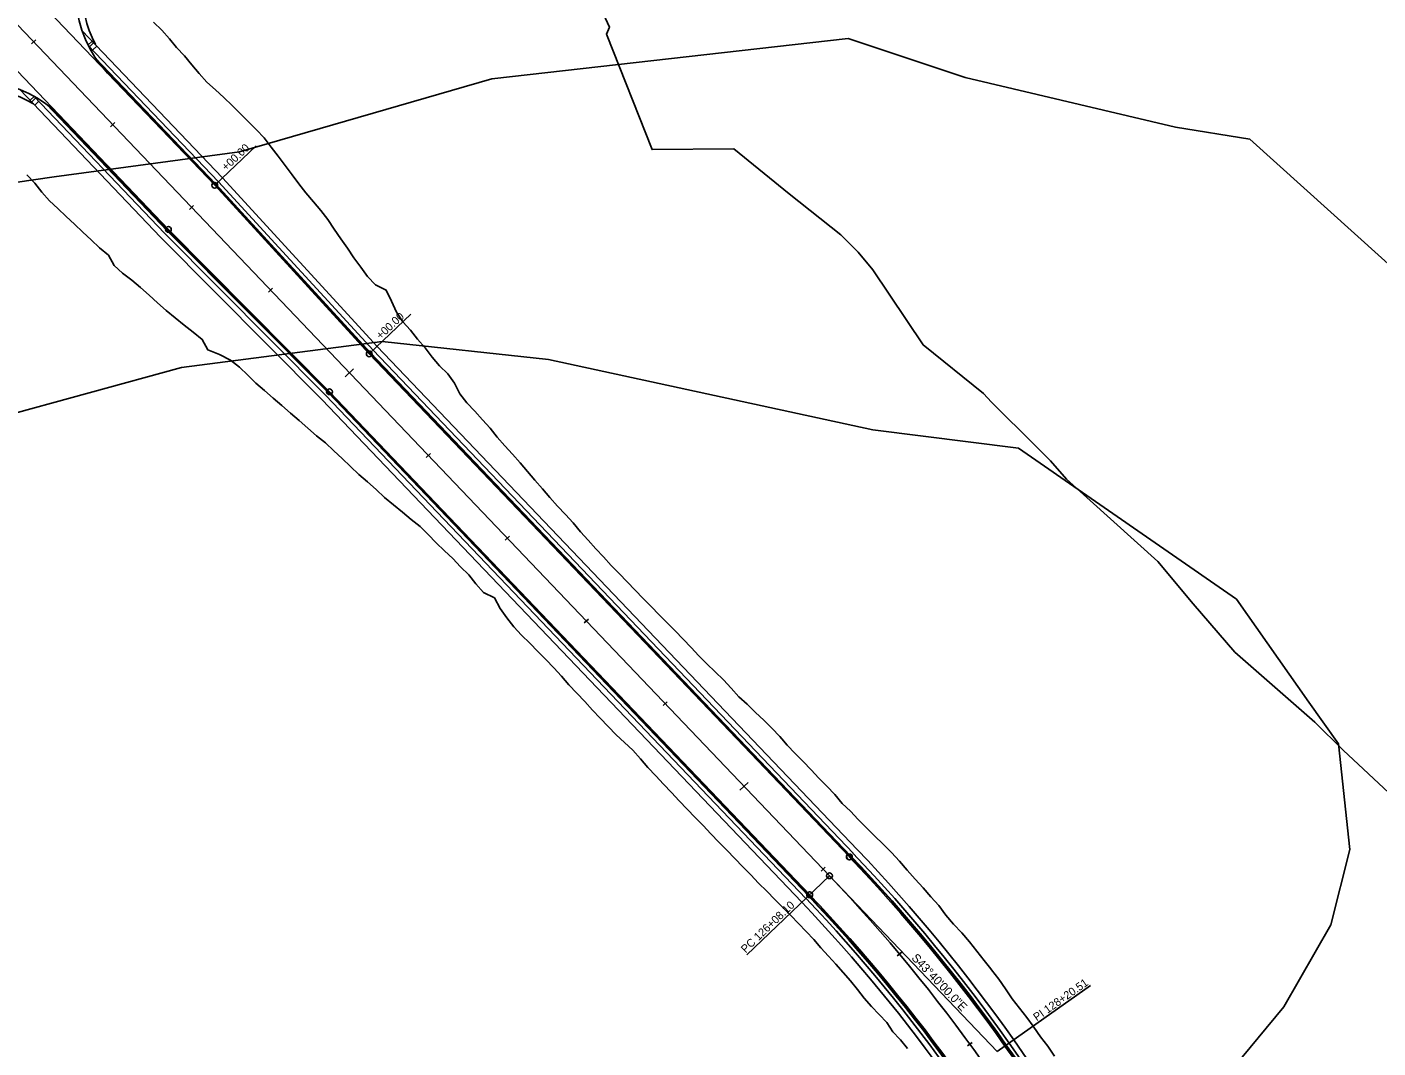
# Model space of a CAD drawing. Extents: x 1300404 to 1323571, y 234004 to 252077.
# Drawn here: x 1311251 to 1312432, y 239629 to 240521 of the extents above; entities that cross this region are included whole.
import ezdxf

# ---------------------------------------------------------------- set-up
doc = ezdxf.new("R2010")
doc.units = 0
for name, color, linetype in [('R_Const Limits', 7, 'Continuous'), ('R_Curb', 7, 'Continuous'), ('R_Flooplain', 7, 'Continuous'), ('R_Horz Alg Annot', 7, 'Continuous'), ('R_Horz Alg Annot Leader', 7, 'Continuous'), ('R_Horz Alg Major Ticks', 7, 'Continuous'), ('R_Horz Alg Minor Ticks', 7, 'Continuous'), ('R_Horz Alg Tangents', 7, 'Continuous'), ('R_Horz Alg Tangents Text', 7, 'Continuous'), ('R_Lane Edge', 7, 'Continuous'), ('R_Proposed', 7, 'Continuous'), ('R_Shoulder', 7, 'Continuous'), ('R_Sidewalk Edge', 7, 'Continuous')]:
    doc.layers.add(name, color=color, linetype=linetype)

msp = doc.modelspace()

# ---------------------------------------------------------------- linework, layer by layer
at = {"layer": 'R_Const Limits'}
for points in [[(1312468.4, 239826.8), (1312401.8, 239888.9), (1312377.1, 239913.6), (1312307.2, 239974.6), (1312270.6, 240016.9), (1312239.7, 240054), (1312160, 240125.9), (1312146, 240142), (1312132.7, 240155.1), (1312094.4, 240193.4), (1312087.2, 240200.9), (1312034.5, 240243.4), (1311990.5, 240309.1), (1311977.8, 240324.5), (1311962.6, 240339.6), (1311917.3, 240375.7), (1311869, 240414.8), (1311797.5, 240414.3), (1311757.6, 240515.1), (1311760.1, 240521.2), (1311745.1, 240554.6)], [(1311361.5, 240525.7), (1311368.6, 240518.6), (1311375.3, 240511.2), (1311381.6, 240503.4), (1311388.6, 240496.2), (1311395, 240488.5), (1311401.3, 240480.7), (1311408.1, 240473.3), (1311415.5, 240466.6), (1311422.8, 240459.8), (1311430.1, 240452.9), (1311437.2, 240445.8), (1311444.2, 240438.7), (1311451.3, 240431.6), (1311458.2, 240424.5), (1311458.2, 240424.4), (1311464.4, 240416.5), (1311470.4, 240408.4), (1311476.4, 240400.3), (1311482.5, 240392.3), (1311488.6, 240384.3), (1311494.7, 240376.3), (1311501.2, 240368.6), (1311507.7, 240361), (1311513.9, 240353.1), (1311519.5, 240344.7), (1311525.2, 240336.3), (1311531, 240328), (1311536.5, 240319.5), (1311542.6, 240311.4), (1311548.4, 240303.2), (1311555.4, 240296), (1311565, 240291.3), (1311569.4, 240281.7), (1311573.8, 240272.1), (1311579.3, 240263.5), (1311586.2, 240256.2), (1311592.4, 240248.4), (1311599.1, 240240.9), (1311605, 240232.7), (1311611.5, 240225.1), (1311618.8, 240218.2), (1311624.6, 240209.9), (1311629.3, 240200.7), (1311635.5, 240192.8), (1311642.3, 240185.4), (1311649, 240177.9), (1311655.8, 240170.6), (1311662, 240162.8), (1311668.6, 240155.2), (1311675.4, 240147.9), (1311682, 240140.4), (1311688.4, 240132.6), (1311694.9, 240125), (1311701.5, 240117.5), (1311708.1, 240109.9), (1311714.8, 240102.5), (1311721.6, 240095.2), (1311728.3, 240087.7), (1311734.8, 240080.1), (1311741.5, 240072.7), (1311748.1, 240065.2), (1311755, 240058), (1311761.7, 240050.6), (1311768.7, 240043.4), (1311775.7, 240036.2), (1311782.5, 240029), (1311789.5, 240021.8), (1311796.5, 240014.6), (1311803.5, 240007.5), (1311810.7, 240000.5), (1311817.7, 239993.4), (1311824.7, 239986.2), (1311831.5, 239978.9), (1311838.2, 239971.5), (1311845.3, 239964.5), (1311852.6, 239957.6), (1311859.8, 239950.6), (1311866.5, 239943.2), (1311873.3, 239935.8), (1311880.7, 239929.1), (1311887.9, 239922.1), (1311895.2, 239915.3), (1311902.3, 239908.2), (1311909.1, 239900.9), (1311911, 239899), (1311915.7, 239893.4), (1311922.6, 239886.2), (1311929.5, 239879), (1311936.5, 239871.8), (1311943.4, 239864.6), (1311950.4, 239857.4), (1311957.2, 239850.1), (1311963.8, 239842.5), (1311971.1, 239835.6), (1311977.8, 239828.3), (1311984.9, 239821.2), (1311992.1, 239814.2), (1311999.5, 239806.9), (1312006.7, 239799.4), (1312013.7, 239791.8), (1312020.6, 239784), (1312027.6, 239776.3), (1312034.5, 239768.6), (1312041.3, 239760.8), (1312048.3, 239753.1), (1312054.3, 239744.6), (1312061, 239736.7), (1312068.3, 239729.3), (1312075, 239721.3), (1312081.4, 239713.2), (1312088, 239705.1), (1312093.8, 239697.8), (1312094.4, 239697), (1312100.6, 239688.7), (1312106.6, 239680.2), (1312112.3, 239671.5), (1312118.7, 239663.4), (1312125.2, 239655.2), (1312130.8, 239647.7), (1312131.3, 239646.9), (1312137.1, 239638.2), (1312143.6, 239630.1), (1312149.3, 239621.5)], [(1312020.9, 239628.2), (1312014.7, 239635.6), (1312014.1, 239636.3), (1312008, 239642.7), (1312002.7, 239650.8), (1311996.1, 239657.9), (1311989.4, 239664.9), (1311982.9, 239672.1), (1311977, 239679.7), (1311970.9, 239687.3), (1311964.5, 239694.5), (1311958.2, 239701.9), (1311951.6, 239708.9), (1311945.1, 239716.1), (1311938.8, 239723.4), (1311932.2, 239730.4), (1311925.5, 239737.4), (1311918.7, 239744.3), (1311911.7, 239751.3), (1311904.7, 239758.5), (1311897.7, 239765.6), (1311890.6, 239772.7), (1311883.8, 239780), (1311876.8, 239787.1), (1311869.8, 239794.2), (1311862.8, 239801.5), (1311855.9, 239808.6), (1311848.9, 239815.8), (1311842, 239823), (1311836.9, 239828.3), (1311835, 239830.2), (1311828.1, 239837.4), (1311821.2, 239844.6), (1311814.3, 239851.9), (1311807.5, 239859.2), (1311800.7, 239866.5), (1311793.8, 239873.8), (1311787.4, 239881.5), (1311780.6, 239888.9), (1311773.4, 239895.8), (1311766, 239902.5), (1311759.1, 239909.8), (1311752, 239916.9), (1311745.2, 239924.1), (1311738.5, 239931.6), (1311731.7, 239938.9), (1311724.7, 239946.1), (1311718.1, 239953.7), (1311711.4, 239961.1), (1311704.6, 239968.4), (1311697.4, 239975.4), (1311690.4, 239982.5), (1311683.3, 239989.5), (1311676.6, 239996.9), (1311670.3, 240004.8), (1311664.5, 240013), (1311659.5, 240022.1), (1311650.1, 240026.9), (1311643.4, 240034.4), (1311637.3, 240042.4), (1311630, 240049.3), (1311623.1, 240056.5), (1311615.8, 240063.4), (1311608.6, 240070.3), (1311601.7, 240077.5), (1311594.5, 240084.5), (1311586.6, 240090.8), (1311579, 240097.3), (1311571.2, 240103.7), (1311563.4, 240110.1), (1311556.1, 240117), (1311548.6, 240123.6), (1311541, 240130.2), (1311533.8, 240137.1), (1311526.5, 240144), (1311519.2, 240150.8), (1311511.9, 240157.7), (1311503.9, 240163.9), (1311496.3, 240170.5), (1311488.9, 240177.2), (1311481.1, 240183.6), (1311473.6, 240190.3), (1311465.9, 240196.8), (1311458.5, 240203.5), (1311450.9, 240210.1), (1311443.8, 240217.1), (1311436.5, 240223.9), (1311428.6, 240230.2), (1311419.1, 240235), (1311408.9, 240239.1), (1311404, 240248.2), (1311396, 240254.5), (1311388.2, 240260.8), (1311380.3, 240267.1), (1311372.5, 240273.5), (1311365, 240280.1), (1311357.5, 240286.8), (1311350.1, 240293.5), (1311342.4, 240300), (1311334.3, 240306.2), (1311334.3, 240306.2), (1311327, 240313), (1311321.9, 240321.9), (1311314.1, 240328.3), (1311306.8, 240335.2), (1311299.5, 240342), (1311292.2, 240348.9), (1311284.9, 240355.7), (1311277.6, 240362.6), (1311270.3, 240369.4), (1311263.6, 240376.9), (1311257.6, 240385), (1311250.7, 240392.2)]]:
    msp.add_lwpolyline(points, dxfattribs=at)
at = {"layer": 'R_Curb'}
for p, q in [((1311310.4, 240494.6), (1311416, 240384.1)), ((1311312.2, 240492), (1311415.6, 240383.7)), ((1311267.7, 240453.9), (1311373.3, 240343.3)), ((1311270.3, 240452), (1311373.6, 240343.7)), ((1311415.6, 240383.7), (1311550.8, 240236.3)), ((1311416, 240384.1), (1311551.2, 240236.6)), ((1311514.3, 240201.4), (1311373.3, 240343.3)), ((1311514.6, 240201.8), (1311373.6, 240343.7)), ((1311550.8, 240236.3), (1311970.7, 239796.4)), ((1311551.2, 240236.6), (1311971.1, 239796.7)), ((1311514.3, 240201.4), (1311934.2, 239761.5)), ((1311514.6, 240201.8), (1311934.5, 239761.8))]:
    msp.add_line(p, q, dxfattribs=at)
for radius in [1457.4, 1457.9, 1406.9, 1407.4]:
    msp.add_arc((1310916.4, 238790.1), radius, 26.7964, 43.6667, dxfattribs=at)
at = {"layer": 'R_Flooplain'}
for p, q in [((1311968.9, 240511.4), (1311657.4, 240476.2)), ((1312071.2, 240477.2), (1311968.9, 240511.4)), ((1311657.4, 240476.2), (1311436.5, 240412.4)), ((1312255.3, 240434), (1312071.2, 240477.2)), ((1312320.2, 240423.5), (1312255.3, 240434)), ((1312507.7, 240254.3), (1312320.2, 240423.5)), ((1311436.5, 240412.4), (1311274.5, 240390.3)), ((1311274.5, 240390.3), (1311123.4, 240368.9)), ((1311385.9, 240223.8), (1311561.3, 240246.4)), ((1311561.3, 240246.4), (1311706.9, 240230.6)), ((1311133.3, 240154.2), (1311385.9, 240223.8)), ((1311706.9, 240230.6), (1311990.5, 240169.1)), ((1311990.5, 240169.1), (1312118, 240153)), ((1312118, 240153), (1312308.6, 240021.2)), ((1312308.6, 240021.2), (1312371.8, 239930.9)), ((1312371.8, 239930.9), (1312397.8, 239894.5)), ((1312397.8, 239894.5), (1312407.8, 239802.1)), ((1312407.8, 239802.1), (1312391.2, 239736.4)), ((1312391.2, 239736.4), (1312350.1, 239664.6)), ((1312350.1, 239664.6), (1312296, 239599.6))]:
    msp.add_line(p, q, dxfattribs=at)
at = {"layer": 'R_Horz Alg Annot Leader'}
for p, q in [((1311414.9, 240383), (1311451.1, 240417.6)), ((1311550.1, 240235.6), (1311586.3, 240270.2))]:
    msp.add_line(p, q, dxfattribs=at)
for points in [[(1311952.6, 239779.2), (1311880.2, 239710.1)], [(1312099.2, 239625.5), (1312180.9, 239683.2)]]:
    msp.add_lwpolyline(points, dxfattribs=at)
at = {"layer": 'R_Horz Alg Major Ticks'}
for points in [[(1311536.3, 240222.5), (1311529.1, 240215.6)], [(1311881.6, 239860.8), (1311874.3, 239853.9)]]:
    msp.add_lwpolyline(points, dxfattribs=at)
at = {"layer": 'R_Horz Alg Minor Ticks'}
for points in [[(1311258.3, 240510.1), (1311254.7, 240506.7)], [(1311327.4, 240437.8), (1311323.8, 240434.3)], [(1311396.4, 240365.4), (1311392.8, 240362)], [(1311465.5, 240293.1), (1311461.9, 240289.6)], [(1311603.6, 240148.4), (1311599.9, 240145)], [(1311672.6, 240076.1), (1311669, 240072.6)], [(1311741.7, 240003.7), (1311738, 240000.3)], [(1311810.7, 239931.4), (1311807.1, 239928)], [(1311948.8, 239786.7), (1311945.2, 239783.3)], [(1312015.8, 239712.3), (1312011.9, 239709.1)], [(1312077.4, 239633.4), (1312073.4, 239630.4)]]:
    msp.add_lwpolyline(points, dxfattribs=at)
at = {"layer": 'R_Horz Alg Tangents'}
msp.add_line((1311952.6, 239779.2), (1312099.2, 239625.5), dxfattribs=at)
at = {"layer": 'R_Lane Edge'}
for p, q in [((1311321.2, 240481.1), (1311414.9, 240383)), ((1311280.7, 240442.5), (1311374.4, 240344.4)), ((1311414.9, 240383), (1311550.1, 240235.6)), ((1311515.3, 240202.5), (1311374.4, 240344.4)), ((1311550.1, 240235.6), (1311970, 239795.7)), ((1311515.3, 240202.5), (1311935.3, 239762.5))]:
    msp.add_line(p, q, dxfattribs=at)
for centre, radius, start, end in [((1311393.6, 240550.2), 100, 143.6667, 223.6667), ((1311208.4, 240373.4), 100, 43.6667, 123.6667), ((1310916.4, 238790.1), 1456.4, 26.7964, 43.6667), ((1310916.4, 238790.1), 1408.4, 26.7964, 43.6667)]:
    msp.add_arc(centre, radius, start, end, dxfattribs=at)
at = {"layer": 'R_Proposed'}
for p, q in [((1310151.8, 241665.8), (1311952.6, 239779.2)), ((1310165.6, 241651.3), (1311952.6, 239779.1)), ((1310165.6, 241651.3), (1311952.6, 239779.1)), ((1310223, 241550.6), (1311374.4, 240344.4)), ((1310682.6, 241150.3), (1311414.9, 240383)), ((1311414.9, 240383), (1311550.1, 240235.6)), ((1311374.4, 240344.4), (1311515.3, 240202.5)), ((1311550.1, 240235.6), (1311970, 239795.7)), ((1311515.3, 240202.5), (1311935.3, 239762.5))]:
    msp.add_line(p, q, dxfattribs=at)
for centre in [(1311414.9, 240383), (1311374.4, 240344.4), (1311550.1, 240235.6), (1311515.3, 240202.5), (1311969.9, 239795.7), (1311970, 239795.7), (1311952.6, 239779.2), (1311935.2, 239762.6), (1311935.3, 239762.5)]:
    msp.add_circle(centre, 2.5, dxfattribs=at)
for radius in [1456.4, 1432.4, 1432.4, 1408.4]:
    msp.add_arc((1310916.4, 238790.1), radius, 26.7964, 43.6667, dxfattribs=at)
at = {"layer": 'R_Shoulder'}
for centre, start, end in [((1311393.6, 240550.2), 143.6667, 207.9824), ((1311208.4, 240373.4), 59.3509, 123.6667)]:
    msp.add_arc(centre, 94, start, end, dxfattribs=at)
at = {"layer": 'R_Sidewalk Edge'}
for p, q in [((1311298.7, 240518.5), (1311421.8, 240389.6)), ((1311307.6, 240509.1), (1311304, 240505.7)), ((1311304, 240505.7), (1311418.1, 240386.1)), ((1311309, 240507.7), (1311305.4, 240504.2)), ((1311311.8, 240504.8), (1311308.2, 240501.4)), ((1311244.5, 240466.7), (1311367.5, 240337.8)), ((1311257, 240460.8), (1311253.4, 240457.4)), ((1311258.4, 240459.4), (1311254.8, 240455.9)), ((1311257, 240460.8), (1311371.1, 240341.2)), ((1311261.1, 240456.5), (1311257.5, 240453)), ((1311421.8, 240389.5), (1311557, 240242.1)), ((1311418.2, 240386.1), (1311553.4, 240238.7)), ((1311512.1, 240199.3), (1311371.1, 240341.2)), ((1311508.5, 240195.8), (1311367.6, 240337.7)), ((1311553.4, 240238.7), (1311973.2, 239798.8)), ((1311557, 240242.1), (1311976.9, 239802.2)), ((1311512.1, 240199.3), (1311932, 239759.4)), ((1311508.5, 240195.8), (1311928.4, 239756))]:
    msp.add_line(p, q, dxfattribs=at)
for radius in [1460.9, 1465.9, 1398.9, 1403.9]:
    msp.add_arc((1310916.4, 238790.1), radius, 26.7964, 43.6667, dxfattribs=at)

# ---------------------------------------------------------------- texts
at = {"layer": 'R_Horz Alg Annot'}
for s, rotation, p in [('+00.00', 43.0769, (1311424.9, 240395.2)), ('+00.00', 43.0769, (1311560.1, 240247.8)), ('PC 126+08.10', 43.6667, (1311879.2, 239711.2)), ('PI 128+20.51', 35.2316, (1312133.9, 239651.8))]:
    msp.add_text(s, height=7, rotation=rotation, dxfattribs=at).set_placement(p)
at = {"layer": 'R_Horz Alg Tangents Text'}
msp.add_text('S43%%d40\'00.0"E', height=7.5, rotation=313.6667, dxfattribs=at).set_placement((1312023.8, 239706.8))

doc.saveas('drawing.dxf')
